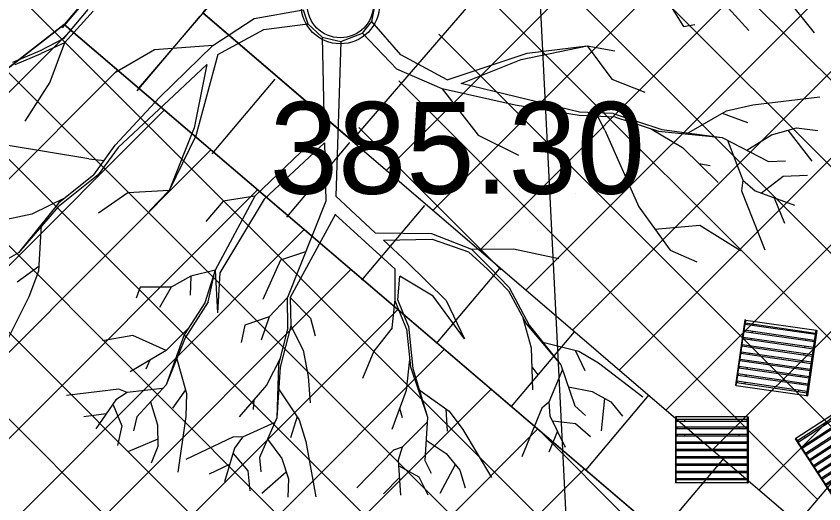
# Model space of a CAD drawing. Extents: x -438233 to -437334, y -1133133 to -1132623.
# Drawn here: x -438064.13 to -438057.53, y -1132956.13 to -1132952.15 of the extents above; entities that cross this region are included whole.
import ezdxf

# ---------------------------------------------------------------- set-up
doc = ezdxf.new("R2010")
doc.units = 0
for name, color, linetype in [('2d web$MIU607', 7, 'Continuous'), ('MOBILIÁŘ', 7, 'Continuous'), ('NADPRAZI', 7, 'Continuous'), ('Vrstva 1', 7, 'Continuous'), ('Vrstva 3', 7, 'Continuous'), ('Vrstva 40', 7, 'Continuous')]:
    doc.layers.add(name, color=color, linetype=linetype)

# ---------------------------------------------------------------- blocks, each defined once
blk = doc.blocks.new('A$C57E965F3')
at = {"layer": '2d web$MIU607'}
for p, q in [((-5892, 5393), (-5950, 5393)), ((-5950, 5393), (-5950, 0)), ((-5881, 5393), (-5892, 5393)), ((-5892, 0), (-5892, 5393)), ((-69, 5393), (-69, 5160)), ((-69, 5393), (-58, 5393)), ((-58, 5393), (0, 5393)), ((-58, 0), (-58, 5393)), ((0, 5393), (0, 0)), ((-69, 5160), (-5881, 5160)), ((-5881, 5043), (-69, 5043)), ((-5881, 4561), (-5881, 5043)), ((-5849, 5086), (-5849, 5080)), ((-5849, 5080), (-5849, 5043)), ((-5186, 5080), (-5186, 5160)), ((-5186, 5043), (-5186, 5080)), ((-758, 5080), (-758, 5160)), ((-758, 5043), (-758, 5080)), ((-101, 5086), (-101, 5080)), ((-101, 5080), (-101, 5043)), ((-5881, 4439), (-69, 4439)), ((-5881, 3961), (-5881, 4439)), ((-5849, 4561), (-5849, 4439)), ((-5849, 3961), (-5849, 3839)), ((-5186, 4439), (-5186, 4561)), ((-5186, 3839), (-5186, 3961)), ((-758, 4439), (-758, 4561)), ((-758, 3839), (-758, 3961)), ((-101, 4561), (-101, 4439)), ((-101, 3961), (-101, 3839)), ((-5881, 3839), (-69, 3839)), ((-5881, 3357), (-5881, 3839)), ((-5849, 3357), (-5849, 3240)), ((-5186, 3240), (-5186, 3357)), ((-758, 3240), (-758, 3357)), ((-101, 3357), (-101, 3240)), ((-5881, 3240), (-69, 3240)), ((-5881, 2757), (-5881, 3240)), ((-5849, 2757), (-5849, 2636)), ((-5186, 2636), (-5186, 2757)), ((-758, 2636), (-758, 2757)), ((-101, 2757), (-101, 2636)), ((-5881, 2636), (-69, 2636)), ((-5881, 2153), (-5881, 2636)), ((-5881, 2036), (-69, 2036)), ((-5881, 1554), (-5881, 2036)), ((-5849, 2153), (-5849, 2036)), ((-5186, 2036), (-5186, 2153)), ((-758, 2036), (-758, 2153)), ((-101, 2153), (-101, 2036)), ((-5881, 1432), (-69, 1432)), ((-5881, 955), (-5881, 1432)), ((-5849, 1554), (-5849, 1432)), ((-5186, 1432), (-5186, 1554)), ((-758, 1432), (-758, 1554)), ((-101, 1554), (-101, 1432)), ((-5881, 833), (-69, 833)), ((-5881, 350), (-5881, 833)), ((-5849, 955), (-5849, 833)), ((-5186, 833), (-5186, 955)), ((-758, 833), (-758, 955)), ((-101, 955), (-101, 833)), ((-5892, 0), (-5950, 0)), ((-5881, 0), (-5892, 0)), ((-69, 233), (-5881, 233)), ((-5849, 350), (-5849, 313)), ((-5849, 313), (-5849, 308)), ((-5186, 313), (-5186, 350)), ((-5186, 233), (-5186, 313)), ((-758, 313), (-758, 350)), ((-758, 233), (-758, 313)), ((-101, 350), (-101, 313)), ((-101, 313), (-101, 308)), ((-69, 0), (-69, 233)), ((-69, 0), (-58, 0)), ((-58, 0), (0, 0))]:
    blk.add_line(p, q, dxfattribs=at)
for points in [[(-69, 5393), (-5881, 5393), (-5881, 5160)], [(-5881, 4561), (-69, 4561), (-69, 5043)], [(-5849, 5086), (-5849, 5117), (-5844, 5144), (-5844, 5155), (-5839, 5160)], [(-101, 5086), (-101, 5144), (-106, 5155), (-106, 5160), (-111, 5160)], [(-5881, 3961), (-69, 3961), (-69, 4439)], [(-5881, 3357), (-69, 3357), (-69, 3839)], [(-5881, 2757), (-69, 2757), (-69, 3240)], [(-5881, 2153), (-69, 2153), (-69, 2636)], [(-5881, 1554), (-69, 1554), (-69, 2036)], [(-5881, 955), (-69, 955), (-69, 1432)], [(-5881, 350), (-69, 350), (-69, 833)], [(-69, 0), (-5881, 0), (-5881, 233)], [(-5849, 308), (-5849, 276), (-5844, 249), (-5844, 239), (-5839, 233)], [(-101, 308), (-101, 249), (-106, 239), (-106, 233), (-111, 233)]]:
    blk.add_lwpolyline(points, dxfattribs=at)

msp = doc.modelspace()

# ---------------------------------------------------------------- linework, layer by layer
at = {"layer": 'DEFPOINTS'}
msp.add_circle((-438057.9618, -1132951.913), 10.2, dxfattribs=at)
at = {"layer": 'MOBILIÁŘ'}
msp.add_lwpolyline([(-438061.5558, -1132950.9015), (-438060.3706, -1132951.9805), (-438061.391, -1132953.1642), (-438062.61, -1132952.1222), (-438061.5558, -1132950.9015)], dxfattribs=at)
for radius in [0.3203, 0.2702]:
    msp.add_circle((-438061.4851, -1132952.0539), radius, dxfattribs=at)
at = {"layer": 'NADPRAZI'}
msp.add_circle((-438057.9618, -1132951.913), 10, dxfattribs=at)
at = {"layer": 'Vrstva 1'}
for p, q in [((-438062.2121, -1132905.0933), (-438059.4745, -1132959.5697)), ((-438058.5493, -1132946.1314), (-438063.7424, -1132952.2168)), ((-438061.1137, -1132953.412), (-438056.5713, -1132948.8696)), ((-438060.7326, -1132953.738), (-438056.1902, -1132949.1956)), ((-438060.3515, -1132954.064), (-438055.8092, -1132949.5216)), ((-438060.4957, -1132949.651), (-438055.9602, -1132954.1865)), ((-438059.9705, -1132954.39), (-438055.4281, -1132949.8476)), ((-438060.8206, -1132950.0332), (-438056.2862, -1132954.5676)), ((-438059.5894, -1132954.7161), (-438055.047, -1132950.1737)), ((-438061.1456, -1132950.4154), (-438056.6122, -1132954.9487)), ((-438059.2083, -1132955.0421), (-438054.6659, -1132950.4997)), ((-438061.4705, -1132950.7975), (-438056.9383, -1132955.3297)), ((-438058.8272, -1132955.3681), (-438054.2848, -1132950.8257)), ((-438058.4462, -1132955.6941), (-438053.9038, -1132951.1518)), ((-438064.887, -1132951.2098), (-438063.8199, -1132952.277)), ((-438057.8809, -1132951.9468), (-438057.6124, -1132952.2838)), ((-438058.8139, -1132952.0193), (-438058.6809, -1132952.233)), ((-438061.2283, -1132952.1911), (-438061.1976, -1132952.0419)), ((-438058.3139, -1132952.0798), (-438058.147, -1132952.2661)), ((-438063.5491, -1132952.0943), (-438063.7507, -1132952.3346)), ((-438063.5039, -1132952.1064), (-438063.7402, -1132952.3653)), ((-438062.1895, -1132952.1661), (-438061.7887, -1132952.0959)), ((-438061.7887, -1132952.0959), (-438061.75, -1132952.2105)), ((-438057.6571, -1132957.4099), (-438063.7424, -1132952.2168)), ((-438062.5266, -1132952.3871), (-438062.1895, -1132952.1661)), ((-438062.1097, -1132952.258), (-438061.75, -1132952.2105)), ((-438061.75, -1132952.2105), (-438061.6339, -1132952.3209)), ((-438061.3025, -1132952.2863), (-438061.2283, -1132952.1911)), ((-438060.9904, -1132952.4653), (-438061.2283, -1132952.1911)), ((-438058.6809, -1132952.233), (-438058.5873, -1132952.2153)), ((-438067.1832, -1132955.7602), (-438063.6871, -1132952.264)), ((-438063.8199, -1132952.277), (-438057.3074, -1132958.7895)), ((-438062.4871, -1132952.4612), (-438062.1097, -1132952.258)), ((-438061.4799, -1132952.3564), (-438061.3025, -1132952.2863)), ((-438061.0234, -1132952.5822), (-438061.3025, -1132952.2863)), ((-438063.7507, -1132952.3346), (-438063.9378, -1132952.4306)), ((-438061.6339, -1132952.3209), (-438061.617, -1132953.0773)), ((-438061.6339, -1132952.3209), (-438061.4799, -1132952.3564)), ((-438060.6809, -1132952.2942), (-438057.2643, -1132955.7108)), ((-438058.0651, -1132956.0202), (-438054.354, -1132952.3091)), ((-438063.7402, -1132952.3653), (-438063.9289, -1132952.4524)), ((-438063.7402, -1132952.3653), (-438063.8587, -1132952.687)), ((-438062.5266, -1132952.3871), (-438063.004, -1132952.4241)), ((-438062.9636, -1132952.8136), (-438062.5266, -1132952.3871)), ((-438061.4799, -1132952.3564), (-438061.5218, -1132953.6192)), ((-438060.0066, -1132952.5008), (-438059.4679, -1132952.3903)), ((-438059.9582, -1132952.4516), (-438059.4679, -1132952.3903)), ((-438059.4679, -1132952.3903), (-438059.2663, -1132952.662)), ((-438059.4679, -1132952.3903), (-438059.2413, -1132952.4314)), ((-438063.9378, -1132952.4306), (-438064.1652, -1132952.5266)), ((-438064.1418, -1132952.5427), (-438063.9289, -1132952.4524)), ((-438063.004, -1132952.4241), (-438063.3217, -1132952.6096)), ((-438062.4871, -1132952.4612), (-438062.6661, -1132953.1265)), ((-438060.613, -1132952.6685), (-438060.9904, -1132952.4653)), ((-438060.613, -1132952.6685), (-438059.9582, -1132952.4516)), ((-438062.8443, -1132952.7943), (-438062.575, -1132952.5435)), ((-438062.575, -1132952.5435), (-438062.6806, -1132953.0604)), ((-438060.4969, -1132952.6975), (-438060.0066, -1132952.5008)), ((-438066.9347, -1132956.2188), (-438063.3055, -1132952.5896)), ((-438064.2178, -1132952.5862), (-438058.0025, -1132958.8015)), ((-438060.6525, -1132952.7427), (-438061.0234, -1132952.5822)), ((-438061.007, -1132952.6753), (-438057.5903, -1132956.0919)), ((-438059.2663, -1132952.662), (-438058.997, -1132952.7701)), ((-438063.8587, -1132952.687), (-438064.0628, -1132953.0056)), ((-438060.6525, -1132952.7427), (-438060.3598, -1132953.1209)), ((-438060.0574, -1132952.8741), (-438060.6525, -1132952.7427)), ((-438060.138, -1132952.7846), (-438060.4969, -1132952.6975)), ((-438063.3241, -1132953.2031), (-438062.9636, -1132952.8136)), ((-438063.3015, -1132953.2201), (-438062.8443, -1132952.7943)), ((-438059.5316, -1132952.9322), (-438060.138, -1132952.7846)), ((-438058.1123, -1132952.8717), (-438057.5656, -1132952.8072)), ((-438059.5332, -1132952.9604), (-438060.0574, -1132952.8741)), ((-438058.3301, -1132952.9201), (-438058.1123, -1132952.8717)), ((-438066.6614, -1132956.6526), (-438062.924, -1132952.9152)), ((-438064.6158, -1132952.8953), (-438058.7588, -1132958.7523)), ((-438059.255, -1132952.9443), (-438059.5316, -1132952.9322)), ((-438059.255, -1132952.9443), (-438058.8566, -1132953.0741)), ((-438058.6567, -1132953.1096), (-438058.3301, -1132952.9201)), ((-438058.3639, -1132952.9394), (-438058.1583, -1132953.0169)), ((-438059.2365, -1132952.9733), (-438059.5332, -1132952.9604)), ((-438059.3236, -1132953.0806), (-438059.3808, -1132952.9669)), ((-438059.2365, -1132952.9733), (-438058.8833, -1132953.0886)), ((-438062.6806, -1132953.0604), (-438062.8838, -1132953.5708)), ((-438061.617, -1132953.0773), (-438062.183, -1132953.6184)), ((-438061.333, -1132953.0564), (-438060.1701, -1132954.2192)), ((-438058.9502, -1132953.0668), (-438058.6889, -1132953.2209)), ((-438058.8566, -1132953.0741), (-438058.3647, -1132953.1386)), ((-438057.9624, -1132953.1168), (-438057.7575, -1132953.0612)), ((-438057.7575, -1132953.0612), (-438057.5817, -1132953.083)), ((-438065.1156, -1132953.1026), (-438059.6005, -1132958.6177)), ((-438062.6661, -1132953.1265), (-438062.8838, -1132953.5708)), ((-438060.3598, -1132953.1209), (-438060.03, -1132953.2846)), ((-438059.3236, -1132953.0806), (-438059.0453, -1132953.7055)), ((-438058.8833, -1132953.0886), (-438058.3647, -1132953.1386)), ((-438058.3647, -1132953.1386), (-438057.9865, -1132953.3346)), ((-438058.1623, -1132953.2426), (-438057.9624, -1132953.1168)), ((-438057.8277, -1132953.0806), (-438057.6325, -1132953.3338)), ((-438065.7209, -1132953.2044), (-438060.609, -1132958.3163)), ((-438063.5402, -1132953.3128), (-438064.2152, -1132953.2015)), ((-438063.4983, -1132953.4434), (-438063.3241, -1132953.2031)), ((-438061.6153, -1132953.1822), (-438062.1072, -1132953.6434)), ((-438061.6153, -1132953.1822), (-438061.6032, -1132953.6587)), ((-438058.3196, -1132953.162), (-438058.1954, -1132953.487)), ((-438066.388, -1132957.0863), (-438062.5425, -1132953.2408)), ((-438063.3015, -1132953.2201), (-438063.4644, -1132953.4442)), ((-438058.6889, -1132953.2209), (-438058.397, -1132953.5079)), ((-438066.3263, -1132953.3061), (-438060.8669, -1132958.7655)), ((-438063.5402, -1132953.3128), (-438063.4136, -1132953.3273)), ((-438057.9865, -1132953.3346), (-438057.847, -1132953.3297)), ((-438058.5551, -1132953.3523), (-438058.4615, -1132953.3676)), ((-438063.4644, -1132953.4442), (-438063.791, -1132953.7063)), ((-438063.4983, -1132953.4434), (-438063.7878, -1132953.6757)), ((-438058.0438, -1132953.5902), (-438057.8648, -1132953.4555)), ((-438057.8648, -1132953.4555), (-438057.668, -1132953.4475)), ((-438058.1954, -1132953.487), (-438058.2059, -1132953.5749)), ((-438058.1954, -1132953.487), (-438058.0954, -1132953.5741)), ((-438066.1147, -1132957.5201), (-438062.161, -1132953.5664)), ((-438063.2217, -1132953.5902), (-438063.4604, -1132953.7563)), ((-438062.8838, -1132953.5708), (-438063.2217, -1132953.5902)), ((-438062.8838, -1132953.5708), (-438063.0435, -1132953.737)), ((-438059.562, -1132953.599), (-438059.562, -1132953.599)), ((-438058.2059, -1132953.5749), (-438058.0156, -1132954.0555)), ((-438058.0954, -1132953.5741), (-438057.772, -1132953.6926)), ((-438063.7338, -1132953.6321), (-438064.0063, -1132953.7652)), ((-438062.4427, -1132953.6579), (-438062.583, -1132953.8249)), ((-438062.183, -1132953.6184), (-438062.5072, -1132954.2216)), ((-438062.1072, -1132953.6434), (-438062.4709, -1132954.245)), ((-438062.183, -1132953.6184), (-438062.4427, -1132953.6579)), ((-438061.6032, -1132953.6587), (-438061.9177, -1132954.4474)), ((-438061.5218, -1132953.6192), (-438061.1992, -1132953.9168)), ((-438057.9382, -1132953.6321), (-438057.8559, -1132953.8378)), ((-438063.7878, -1132953.6757), (-438064.1144, -1132954.0813)), ((-438063.791, -1132953.7063), (-438064.1144, -1132954.0813)), ((-438059.0453, -1132953.7055), (-438058.7889, -1132954.0603)), ((-438064.0063, -1132953.7652), (-438064.4063, -1132953.8515)), ((-438061.5258, -1132953.7652), (-438061.8944, -1132954.4466)), ((-438061.5266, -1132953.7684), (-438061.038, -1132954.2135)), ((-438063.9313, -1132953.8523), (-438063.9523, -1132954.2297)), ((-438058.9139, -1132953.8878), (-438058.5478, -1132953.8547)), ((-438058.5478, -1132953.8547), (-438058.2131, -1132954.0619)), ((-438065.8414, -1132957.9539), (-438061.7794, -1132953.8919)), ((-438061.1992, -1132953.9168), (-438060.7388, -1132953.9232)), ((-438060.7388, -1132953.9232), (-438060.4122, -1132954.0523)), ((-438061.1323, -1132953.9789), (-438060.7331, -1132953.9692)), ((-438061.1323, -1132953.9789), (-438060.9388, -1132954.1571)), ((-438060.7331, -1132953.9692), (-438060.4372, -1132954.0724)), ((-438060.4122, -1132954.0523), (-438060.0703, -1132954.0482)), ((-438060.4122, -1132954.0523), (-438060.2646, -1132954.1974)), ((-438060.0703, -1132954.0482), (-438059.6993, -1132954.1273)), ((-438058.7889, -1132954.0603), (-438058.572, -1132954.1555)), ((-438064.1144, -1132954.0813), (-438064.4877, -1132954.2893)), ((-438061.7694, -1132954.074), (-438061.9734, -1132954.1402)), ((-438060.4372, -1132954.0724), (-438060.2816, -1132954.2135)), ((-438063.9491, -1132954.1918), (-438064.1273, -1132954.32)), ((-438061.9734, -1132954.1402), (-438062.1185, -1132954.4619)), ((-438060.9388, -1132954.1571), (-438060.6194, -1132954.4708)), ((-438060.2646, -1132954.1974), (-438060.105, -1132954.3643)), ((-438065.5472, -1132958.3668), (-438061.3979, -1132954.2175)), ((-438063.9523, -1132954.2297), (-438064.0313, -1132954.4393)), ((-438062.5072, -1132954.2216), (-438062.7072, -1132954.2724)), ((-438062.5072, -1132954.2216), (-438062.5935, -1132954.4901)), ((-438062.5661, -1132954.4821), (-438062.5072, -1132954.2216)), ((-438062.5072, -1132954.2216), (-438062.4887, -1132954.57)), ((-438062.4709, -1132954.245), (-438062.4887, -1132954.57)), ((-438061.0372, -1132954.4619), (-438061.038, -1132954.2135)), ((-438060.1106, -1132954.3926), (-438060.2816, -1132954.2135)), ((-438062.7072, -1132954.2724), (-438062.8669, -1132954.3619)), ((-438062.7072, -1132954.2724), (-438062.7129, -1132954.4264)), ((-438061.0146, -1132954.4651), (-438060.9984, -1132954.2732)), ((-438060.7267, -1132954.4353), (-438060.9984, -1132954.2732)), ((-438063.1201, -1132954.3627), (-438063.1531, -1132954.4522)), ((-438062.8669, -1132954.3619), (-438063.1201, -1132954.3627)), ((-438062.8669, -1132954.3619), (-438062.962, -1132954.5289)), ((-438060.1106, -1132954.3926), (-438059.9646, -1132954.6651)), ((-438060.105, -1132954.3643), (-438059.9405, -1132954.6716)), ((-438064.0313, -1132954.4393), (-438064.2789, -1132954.9304)), ((-438061.9177, -1132954.4474), (-438062.0653, -1132954.6047)), ((-438061.9129, -1132954.6942), (-438061.9177, -1132954.4474)), ((-438061.8944, -1132954.4466), (-438061.7282, -1132954.6159)), ((-438061.8944, -1132954.4466), (-438061.8895, -1132954.6772)), ((-438061.0605, -1132954.6925), (-438061.0372, -1132954.4619)), ((-438060.9291, -1132954.6796), (-438061.0146, -1132954.4651)), ((-438060.4711, -1132954.7837), (-438060.7267, -1132954.4353)), ((-438062.5935, -1132954.4901), (-438062.7604, -1132954.7506)), ((-438062.5661, -1132954.4821), (-438062.754, -1132954.7748)), ((-438060.9444, -1132954.703), (-438061.0363, -1132954.474)), ((-438060.6194, -1132954.4708), (-438060.4711, -1132954.7837)), ((-438065.1776, -1132958.7043), (-438061.0164, -1132954.5431)), ((-438062.0653, -1132954.6047), (-438062.2645, -1132954.6724)), ((-438062.0653, -1132954.6047), (-438062.1322, -1132954.7958)), ((-438061.7282, -1132954.6159), (-438061.6895, -1132954.7603)), ((-438059.9921, -1132954.6135), (-438059.9243, -1132954.8579)), ((-438062.729, -1132954.7006), (-438062.9088, -1132954.8796)), ((-438062.2645, -1132954.6724), (-438062.2968, -1132954.8127)), ((-438061.9129, -1132954.6942), (-438061.9895, -1132954.9933)), ((-438061.8895, -1132954.6772), (-438061.9758, -1132955.0151)), ((-438061.8895, -1132954.6772), (-438061.7887, -1132954.8772)), ((-438061.0605, -1132954.6925), (-438061.2105, -1132954.8845)), ((-438060.9444, -1132954.703), (-438060.9122, -1132955.0111)), ((-438060.9291, -1132954.6796), (-438060.892, -1132955.0272)), ((-438059.9646, -1132954.6651), (-438059.6816, -1132954.9949)), ((-438059.9405, -1132954.6716), (-438059.6816, -1132954.9949)), ((-438063.1814, -1132954.7563), (-438063.4281, -1132954.7998)), ((-438062.9088, -1132954.8796), (-438063.1814, -1132954.7563)), ((-438062.7604, -1132954.7506), (-438062.9096, -1132955.1586)), ((-438062.754, -1132954.7748), (-438062.9096, -1132955.1586)), ((-438059.9243, -1132954.8579), (-438059.9146, -1132955.199)), ((-438059.8413, -1132954.8095), (-438059.5348, -1132954.8837)), ((-438064.8079, -1132959.0417), (-438060.6349, -1132954.8687)), ((-438062.9088, -1132954.8796), (-438063.2015, -1132955.0538)), ((-438061.7887, -1132954.8772), (-438061.7484, -1132955.0917)), ((-438061.2105, -1132954.8845), (-438061.3049, -1132955.1087)), ((-438059.5663, -1132954.8756), (-438059.4873, -1132955.0417)), ((-438059.5348, -1132954.8837), (-438059.376, -1132954.9804)), ((-438063.0427, -1132954.9587), (-438063.0749, -1132955.0312)), ((-438062.8258, -1132954.9288), (-438062.7419, -1132955.2312)), ((-438061.975, -1132954.9377), (-438062.0895, -1132955.1635)), ((-438061.9895, -1132954.9933), (-438062.0032, -1132955.428)), ((-438060.9186, -1132954.953), (-438060.9468, -1132955.2046)), ((-438059.376, -1132954.9804), (-438059.0115, -1132955.2578)), ((-438061.9758, -1132955.0151), (-438062.0032, -1132955.428)), ((-438060.9122, -1132955.0111), (-438060.7735, -1132955.4231)), ((-438060.892, -1132955.0272), (-438060.7735, -1132955.4231)), ((-438059.9195, -1132955.0135), (-438059.8719, -1132955.0772)), ((-438059.6679, -1132955.0353), (-438059.7816, -1132955.3022)), ((-438059.6816, -1132954.9949), (-438059.5679, -1132955.332)), ((-438061.7484, -1132955.0917), (-438061.7315, -1132955.3054)), ((-438062.9386, -1132955.1893), (-438063.2265, -1132955.2207)), ((-438062.9096, -1132955.1586), (-438063.1491, -1132955.4215)), ((-438062.0895, -1132955.1635), (-438062.3129, -1132955.4207)), ((-438061.9952, -1132955.1836), (-438061.8202, -1132955.4449)), ((-438060.8517, -1132955.1909), (-438060.5952, -1132955.3748)), ((-438059.6211, -1132955.1756), (-438059.4276, -1132955.2143)), ((-438064.4383, -1132959.3792), (-438060.2533, -1132955.1943)), ((-438063.2959, -1132955.1941), (-438063.7225, -1132955.2457)), ((-438063.2265, -1132955.2207), (-438063.3185, -1132955.2828)), ((-438063.2265, -1132955.2207), (-438063.2959, -1132955.1941)), ((-438062.7499, -1132955.2014), (-438062.8564, -1132955.3498)), ((-438062.7419, -1132955.2312), (-438062.7483, -1132955.4183)), ((-438060.9468, -1132955.2046), (-438061.0654, -1132955.5239)), ((-438059.4276, -1132955.2143), (-438059.2736, -1132955.299)), ((-438063.3185, -1132955.2828), (-438063.4822, -1132955.5191)), ((-438063.3427, -1132955.3215), (-438063.2717, -1132955.4941)), ((-438063.0378, -1132955.299), (-438062.9782, -1132955.4869)), ((-438062.1911, -1132955.2812), (-438062.1984, -1132955.3602)), ((-438059.7816, -1132955.3022), (-438059.838, -1132955.349)), ((-438059.7816, -1132955.3022), (-438059.7719, -1132955.4119)), ((-438059.3252, -1132955.2707), (-438059.3542, -1132955.536)), ((-438059.2736, -1132955.299), (-438059.1792, -1132955.4143)), ((-438061.0009, -1132955.3506), (-438060.9799, -1132955.4272)), ((-438060.6219, -1132955.3562), (-438060.6106, -1132955.5385)), ((-438060.5952, -1132955.3748), (-438060.484, -1132955.5239)), ((-438059.838, -1132955.349), (-438060.0009, -1132955.7473)), ((-438059.5679, -1132955.332), (-438059.4816, -1132955.4094)), ((-438063.3983, -1132955.3973), (-438063.5822, -1132955.4199)), ((-438063.1491, -1132955.4215), (-438063.1741, -1132955.5352)), ((-438062.7483, -1132955.4183), (-438062.8128, -1132955.8723)), ((-438062.0032, -1132955.428), (-438062.1468, -1132955.7538)), ((-438061.8379, -1132955.4183), (-438061.8911, -1132955.5933)), ((-438061.8202, -1132955.4449), (-438061.7678, -1132955.6231)), ((-438060.7735, -1132955.4231), (-438060.7936, -1132955.7772)), ((-438059.7719, -1132955.4119), (-438059.6461, -1132955.6699)), ((-438059.7493, -1132955.4522), (-438059.5639, -1132955.4748)), ((-438064.0686, -1132959.7166), (-438059.8718, -1132955.5199)), ((-438063.2717, -1132955.4941), (-438063.3072, -1132955.6546)), ((-438062.9782, -1132955.4869), (-438062.9765, -1132955.6635)), ((-438062.0202, -1132955.4667), (-438062.2838, -1132955.5877)), ((-438060.7751, -1132955.4651), (-438060.9799, -1132955.6699)), ((-438059.5639, -1132955.4748), (-438059.4413, -1132955.5828)), ((-438062.3572, -1132955.5844), (-438062.7475, -1132955.7683)), ((-438062.2838, -1132955.5877), (-438062.3572, -1132955.5844)), ((-438060.484, -1132955.5239), (-438060.2493, -1132955.9175)), ((-438059.8589, -1132955.5309), (-438056.7087, -1132958.6811)), ((-438059.7098, -1132955.5377), (-438059.78, -1132955.7102)), ((-438062.9765, -1132955.603), (-438063.2225, -1132955.7078)), ((-438062.2838, -1132955.5877), (-438062.3508, -1132955.6756)), ((-438062.0798, -1132955.603), (-438061.9637, -1132955.761)), ((-438061.7678, -1132955.6231), (-438061.6855, -1132956.0747)), ((-438060.7839, -1132955.6127), (-438060.6194, -1132955.7215)), ((-438062.9765, -1132955.6635), (-438063.0322, -1132955.8005)), ((-438062.3508, -1132955.6756), (-438062.4322, -1132955.9505)), ((-438062.3613, -1132955.7191), (-438062.2403, -1132955.8618)), ((-438061.0509, -1132955.6933), (-438061.3508, -1132956.0005)), ((-438060.9799, -1132955.6699), (-438061.0509, -1132955.6933)), ((-438060.9799, -1132955.6699), (-438061.013, -1132955.7755)), ((-438062.1468, -1132955.7538), (-438062.1347, -1132955.8699)), ((-438061.9637, -1132955.761), (-438061.9073, -1132955.928)), ((-438061.013, -1132955.7755), (-438060.9928, -1132956.0618)), ((-438060.7936, -1132955.7772), (-438060.742, -1132955.882)), ((-438060.6194, -1132955.7215), (-438060.5082, -1132955.8578)), ((-438063.6989, -1132960.0541), (-438059.4903, -1132955.8454)), ((-438062.3903, -1132955.8094), (-438062.558, -1132955.8892)), ((-438061.0073, -1132955.8207), (-438060.8436, -1132955.911)), ((-438060.5461, -1132955.8118), (-438060.6719, -1132956.0465)), ((-438062.2403, -1132955.8618), (-438062.2234, -1132956.0239)), ((-438061.9266, -1132955.8715), (-438062.1258, -1132956.0473)), ((-438061.0025, -1132955.9159), (-438061.1315, -1132956.0489)), ((-438060.8436, -1132955.911), (-438060.7702, -1132956.0586)), ((-438060.5082, -1132955.8578), (-438060.4646, -1132955.9997)), ((-438061.9073, -1132955.928), (-438061.9153, -1132956.0763))]:
    msp.add_line(p, q, dxfattribs=at)
for points in [[(-438058.5493, -1132946.1314), (-438063.7424, -1132952.2168), (-438064.8182, -1132953.0526), (-438064.9161, -1132952.0742)], [(-438066.9447, -1132951.5718), (-438066.7906, -1132953.3842), (-438064.8182, -1132953.0526), (-438063.7424, -1132952.2168), (-438057.6571, -1132957.4099), (-438054.2884, -1132957.7853), (-438055.9248, -1132958.5393), (-438057.5402, -1132958.8316), (-438059.2588, -1132958.7198), (-438060.6698, -1132958.2981), (-438061.447, -1132960.141), (-438060.0002, -1132960.6255), (-438058.2795, -1132960.8791), (-438056.7156, -1132960.7888), (-438055.1087, -1132960.4181), (-438054.2265, -1132960.0218), (-438053.2269, -1132959.4804), (-438054.3038, -1132957.7953), (-438057.6571, -1132957.4099), (-438052.464, -1132951.3245)]]:
    msp.add_lwpolyline(points, dxfattribs=at)
at = {"layer": 'Vrstva 40'}
for p, q in [((-438057.9408, -1132946.6507), (-438063.1339, -1132952.7361)), ((-438053.0725, -1132950.8052), (-438058.2656, -1132956.8906)), ((-438063.2446, -1132951.6325), (-438063.759, -1132952.2426)), ((-438062.633, -1132952.1481), (-438063.1474, -1132952.7583)), ((-438062.61, -1132952.1222), (-438057.1449, -1132956.8019)), ((-438062.0214, -1132952.6638), (-438062.5358, -1132953.2739)), ((-438061.4098, -1132953.1795), (-438061.9242, -1132953.7896)), ((-438060.7982, -1132953.6952), (-438061.3126, -1132954.3053)), ((-438060.1865, -1132954.2109), (-438060.701, -1132954.821)), ((-438059.5749, -1132954.7266), (-438060.0894, -1132955.3367)), ((-438058.9633, -1132955.2423), (-438059.4778, -1132955.8524)), ((-438058.3517, -1132955.758), (-438058.8662, -1132956.3681))]:
    msp.add_line(p, q, dxfattribs=at)
msp.add_circle((-438057.9725, -1132951.9018), 9.9418, dxfattribs=at)
msp.add_arc((-438057.9725, -1132951.9018), 6.9418, 139.844, 189.5425, dxfattribs=at)

# ---------------------------------------------------------------- block references
at = {"layer": 'MOBILIÁŘ', "xscale": 0.0001}
for p, yscale, rotation in [((-438058.2561, -1132955.1635), -0.00010000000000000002, 171.76168090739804), ((-438056.9752, -1132955.7294), 0.00010000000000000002, 33.00744973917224)]:
    msp.add_blockref('A$C57E965F3', p, dxfattribs=dict(at, yscale=yscale, rotation=rotation))
at = {"layer": 'MOBILIÁŘ', "xscale": 0.0001, "yscale": 9.999999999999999e-05}
msp.add_blockref('A$C57E965F3', (-438058.1508, -1132955.9594), dxfattribs=at)

# ---------------------------------------------------------------- texts
at = {"layer": 'Vrstva 3'}
msp.add_text('385.30 ', height=0.75, dxfattribs=at).set_placement((-438062.062, -1132953.599))

doc.saveas('drawing.dxf')
